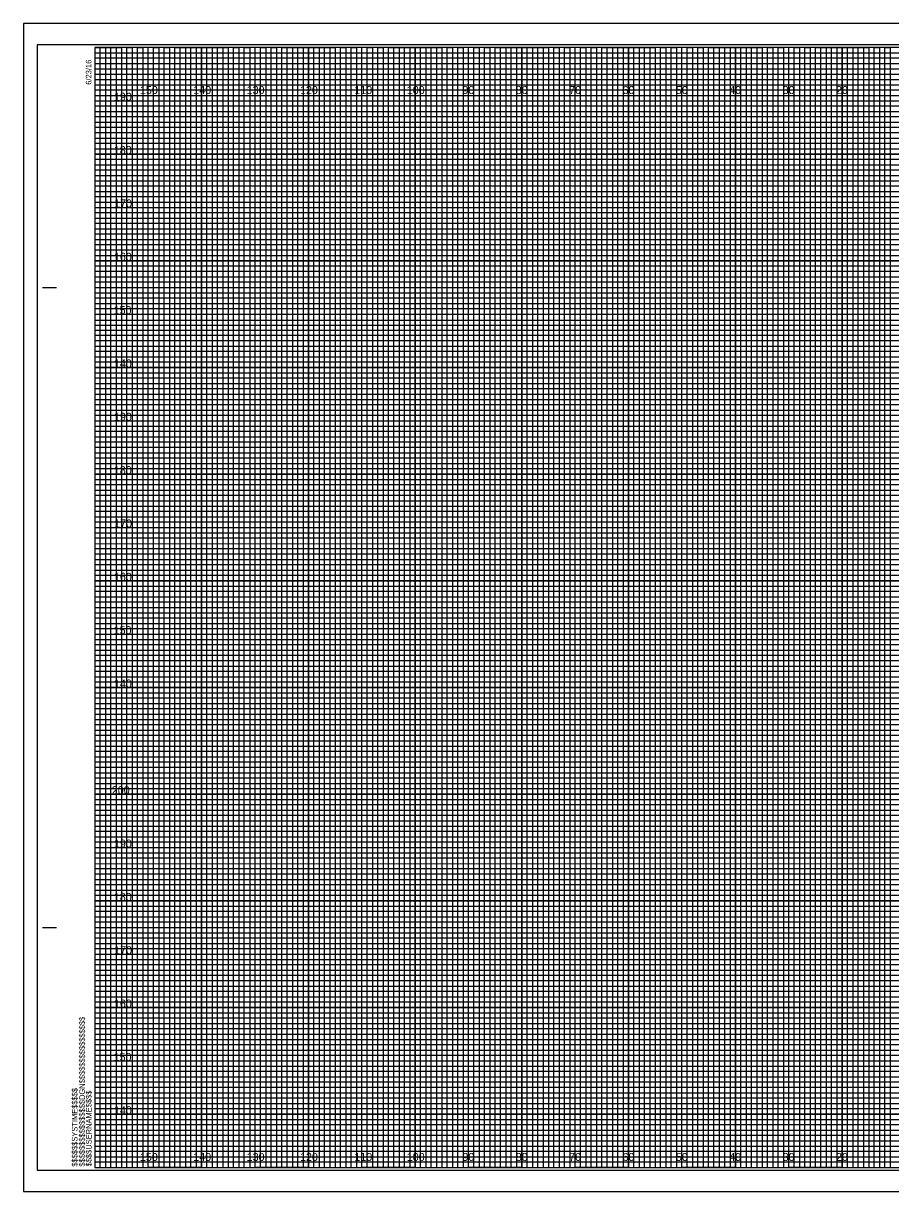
# Model space of a CAD drawing. Extents: x -13 to 323, y -5 to 1754.
# Drawn here: x -13.4 to 149.1, y -4.5 to 214.5 of the extents above; entities that cross this region are included whole.
import ezdxf

# ---------------------------------------------------------------- set-up
doc = ezdxf.new("R2010")
doc.units = 0
for name, color, linetype in [('Exist Cross Section Cell', 7, 'Continuous'), ('Exist XS Center Line Elevation Label', 7, 'Continuous'), ('Exist XS Ground Line', 7, 'Continuous'), ('Prop CMT Pvmt Course 1', 7, 'Continuous'), ('Prop CMT Pvmt Course 2', 7, 'Continuous'), ('Prop CMT Pvmt Course 3', 7, 'Continuous'), ('Prop CMT Shld Paved Course 1', 7, 'Continuous'), ('Prop CMT Shld Paved Course 2', 7, 'Continuous'), ('Prop CMT Subgrade Earthwork', 7, 'Continuous'), ('Prop XS Ditch Standard Text', 7, 'Continuous'), ('Scratch_Level_0', 7, 'Continuous')]:
    doc.layers.add(name, color=color, linetype=linetype)

msp = doc.modelspace()

# ---------------------------------------------------------------- linework, layer by layer
at = {"layer": 'Exist XS Center Line Elevation Label'}
for points in [[(0, 210), (5, 210), (5, 0), (15, 0), (15, 210), (25, 210), (25, 0), (35, 0), (35, 210), (45, 210), (45, 0), (55, 0), (55, 210), (65, 210), (65, 0), (75, 0), (75, 210), (85, 210), (85, 0), (95, 0), (95, 210), (105, 210), (105, 0), (115, 0), (115, 210), (125, 210), (125, 0), (135, 0), (135, 210), (145, 210), (145, 0), (155, 0)], [(0, 205), (275, 205)], [(0, 185), (320, 185), (320, 195), (0, 195)], [(0, 165), (320, 165), (320, 175), (0, 175)], [(0, 145), (320, 145), (320, 155), (0, 155)], [(0, 125), (320, 125), (320, 135), (0, 135)], [(0, 105), (320, 105), (320, 115), (0, 115)], [(0, 85), (320, 85), (320, 95), (0, 95)], [(0, 65), (320, 65), (320, 75), (0, 75)], [(0, 45), (320, 45), (320, 55), (0, 55)], [(0, 25), (320, 25), (320, 35), (0, 35)], [(0, 5), (320, 5), (320, 15), (0, 15)]]:
    msp.add_lwpolyline(points, dxfattribs=at)
at = {"layer": 'Exist XS Ground Line'}
for p, q in [((10, 210), (0, 210)), ((10, 0), (10, 210)), ((30, 210), (20, 210)), ((20, 210), (20, 0)), ((30, 0), (30, 210)), ((50, 210), (40, 210)), ((40, 210), (40, 0)), ((50, 0), (50, 210)), ((70, 210), (60, 210)), ((60, 210), (60, 0)), ((70, 0), (70, 210)), ((90, 210), (80, 210)), ((80, 210), (80, 0)), ((90, 0), (90, 210)), ((110, 210), (100, 210)), ((100, 210), (100, 0)), ((110, 0), (110, 210)), ((130, 210), (120, 210)), ((120, 210), (120, 0)), ((130, 0), (130, 210)), ((150, 210), (140, 210)), ((140, 210), (140, 0)), ((20, 0), (10, 0)), ((40, 0), (30, 0)), ((60, 0), (50, 0)), ((80, 0), (70, 0)), ((100, 0), (90, 0)), ((120, 0), (110, 0)), ((140, 0), (130, 0))]:
    msp.add_line(p, q, dxfattribs=at)
for points in [[(0, 200), (320, 200), (320, 190), (0, 190)], [(0, 180), (320, 180), (320, 170), (0, 170)], [(0, 160), (320, 160), (320, 150), (0, 150)], [(0, 140), (320, 140), (320, 130), (0, 130)], [(0, 120), (320, 120), (320, 110), (0, 110)], [(0, 100), (320, 100), (320, 90), (0, 90)], [(0, 80), (320, 80), (320, 70), (0, 70)], [(0, 60), (320, 60), (320, 50), (0, 50)], [(0, 40), (320, 40), (320, 30), (0, 30)], [(0, 20), (320, 20), (320, 10), (0, 10)]]:
    msp.add_lwpolyline(points, dxfattribs=at)
at = {"layer": 'Prop CMT Pvmt Course 1'}
for p, q in [((323.3, 214.5), (-13.4, 214.5)), ((-13.4, 214.5), (-13.4, -4.5)), ((-13.4, -4.5), (323.3, -4.5))]:
    msp.add_line(p, q, dxfattribs=at)
at = {"layer": 'Prop CMT Pvmt Course 2'}
msp.add_lwpolyline([(-13.4, -4.5), (323.3, -4.5), (323.3, 214.5), (-13.4, 214.5)], close=True, dxfattribs=at)
at = {"layer": 'Prop CMT Pvmt Course 3'}
msp.add_lwpolyline([(-10.8, -0.5), (322.4, -0.5), (322.4, 210.5), (-10.8, 210.5)], close=True, dxfattribs=at)
at = {"layer": 'Prop CMT Shld Paved Course 1'}
for p, q in [((-9.8, 165), (-7.3, 165)), ((-9.7, 165), (-7.2, 165)), ((-9.8, 45), (-7.3, 45)), ((-9.7, 45), (-7.2, 45)), ((0, 0), (0, 0)), ((0, 0), (0, 0)), ((0, 0), (0, 0)), ((0, 0), (0, 0)), ((0, 0), (0, 0)), ((0, 0), (0, 0)), ((0, 0), (0, 0))]:
    msp.add_line(p, q, dxfattribs=at)
msp.add_lwpolyline([(320, 210), (0, 210), (0, 0), (320, 0)], close=True, dxfattribs=at)
at = {"layer": 'Prop CMT Shld Paved Course 2'}
for points in [[(0, 0), (1, 0), (1, 210), (2, 210), (2, 0)], [(2, 0), (3, 0), (3, 210), (4, 210), (4, 0)], [(5, 0), (6, 0), (6, 210), (7, 210), (7, 0)], [(7, 0), (8, 0), (8, 210), (9, 210), (9, 0)], [(10, 0), (11, 0), (11, 210), (12, 210), (12, 0)], [(12, 0), (13, 0), (13, 210), (14, 210), (14, 0)], [(15, 0), (16, 0), (16, 210), (17, 210), (17, 0)], [(17, 0), (18, 0), (18, 210), (19, 210), (19, 0)], [(20, 0), (21, 0), (21, 210), (22, 210), (22, 0)], [(22, 0), (23, 0), (23, 210), (24, 210), (24, 0)], [(25, 0), (26, 0), (26, 210), (27, 210), (27, 0)], [(27, 0), (28, 0), (28, 210), (29, 210), (29, 0)], [(30, 0), (31, 0), (31, 210), (32, 210), (32, 0)], [(32, 0), (33, 0), (33, 210), (34, 210), (34, 0)], [(35, 0), (36, 0), (36, 210), (37, 210), (37, 0)], [(37, 0), (38, 0), (38, 210), (39, 210), (39, 0)], [(40, 0), (41, 0), (41, 210), (42, 210), (42, 0)], [(42, 0), (43, 0), (43, 210), (44, 210), (44, 0)], [(45, 0), (46, 0), (46, 210), (47, 210), (47, 0)], [(47, 0), (48, 0), (48, 210), (49, 210), (49, 0)], [(50, 0), (51, 0), (51, 210), (52, 210), (52, 0)], [(52, 0), (53, 0), (53, 210), (54, 210), (54, 0)], [(55, 0), (56, 0), (56, 210), (57, 210), (57, 0)], [(57, 0), (58, 0), (58, 210), (59, 210), (59, 0)], [(60, 0), (61, 0), (61, 210), (62, 210), (62, 0)], [(62, 0), (63, 0), (63, 210), (64, 210), (64, 0)], [(65, 0), (66, 0), (66, 210), (67, 210), (67, 0)], [(67, 0), (68, 0), (68, 210), (69, 210), (69, 0)], [(70, 0), (71, 0), (71, 210), (72, 210), (72, 0)], [(72, 0), (73, 0), (73, 210), (74, 210), (74, 0)], [(75, 0), (76, 0), (76, 210), (77, 210), (77, 0)], [(77, 0), (78, 0), (78, 210), (79, 210), (79, 0)], [(80, 0), (81, 0), (81, 210), (82, 210), (82, 0)], [(82, 0), (83, 0), (83, 210), (84, 210), (84, 0)], [(85, 0), (86, 0), (86, 210), (87, 210), (87, 0)], [(87, 0), (88, 0), (88, 210), (89, 210), (89, 0)], [(90, 0), (91, 0), (91, 210), (92, 210), (92, 0)], [(92, 0), (93, 0), (93, 210), (94, 210), (94, 0)], [(95, 0), (96, 0), (96, 210), (97, 210), (97, 0)], [(97, 0), (98, 0), (98, 210), (99, 210), (99, 0)], [(100, 0), (101, 0), (101, 210), (102, 210), (102, 0)], [(102, 0), (103, 0), (103, 210), (104, 210), (104, 0)], [(105, 0), (106, 0), (106, 210), (107, 210), (107, 0)], [(107, 0), (108, 0), (108, 210), (109, 210), (109, 0)], [(110, 0), (111, 0), (111, 210), (112, 210), (112, 0)], [(112, 0), (113, 0), (113, 210), (114, 210), (114, 0)], [(115, 0), (116, 0), (116, 210), (117, 210), (117, 0)], [(117, 0), (118, 0), (118, 210), (119, 210), (119, 0)], [(120, 0), (121, 0), (121, 210), (122, 210), (122, 0)], [(122, 0), (123, 0), (123, 210), (124, 210), (124, 0)], [(125, 0), (126, 0), (126, 210), (127, 210), (127, 0)], [(127, 0), (128, 0), (128, 210), (129, 210), (129, 0)], [(130, 0), (131, 0), (131, 210), (132, 210), (132, 0)], [(132, 0), (133, 0), (133, 210), (134, 210), (134, 0)], [(135, 0), (136, 0), (136, 210), (137, 210), (137, 0)], [(137, 0), (138, 0), (138, 210), (139, 210), (139, 0)], [(140, 0), (141, 0), (141, 210), (142, 210), (142, 0)], [(142, 0), (143, 0), (143, 210), (144, 210), (144, 0)], [(145, 0), (146, 0), (146, 210), (147, 210), (147, 0)], [(147, 0), (148, 0), (148, 210), (149, 210), (149, 0)]]:
    msp.add_lwpolyline(points, dxfattribs=at)
at = {"layer": 'Prop CMT Subgrade Earthwork'}
for p, q in [((10, 0), (10, 210)), ((20, 0), (20, 210)), ((30, 0), (30, 210)), ((40, 0), (40, 210)), ((50, 0), (50, 210)), ((60, 0), (60, 210)), ((70, 0), (70, 210)), ((80, 0), (80, 210)), ((90, 0), (90, 210)), ((100, 0), (100, 210)), ((110, 0), (110, 210)), ((120, 0), (120, 210)), ((130, 0), (130, 210)), ((140, 0), (140, 210)), ((0, 200), (320, 200)), ((0, 190), (320, 190)), ((0, 180), (320, 180)), ((0, 170), (320, 170)), ((0, 160), (320, 160)), ((0, 150), (320, 150)), ((0, 140), (320, 140)), ((0, 130), (320, 130)), ((0, 120), (320, 120)), ((0, 110), (320, 110)), ((0, 100), (320, 100)), ((0, 90), (320, 90)), ((0, 80), (320, 80)), ((0, 70), (320, 70)), ((0, 60), (320, 60)), ((0, 50), (320, 50)), ((0, 40), (320, 40)), ((0, 30), (320, 30)), ((0, 20), (320, 20)), ((0, 10), (320, 10))]:
    msp.add_line(p, q, dxfattribs=at)
at = {"layer": 'Scratch_Level_0'}
for p, q in [((0, 209), (260, 209)), ((260, 207.98), (0, 207.98)), ((0, 207.98), (0, 207)), ((0, 207), (260, 207)), ((260, 205.89), (0, 205.89)), ((0, 205.89), (0, 204)), ((0, 204), (320, 204))]:
    msp.add_line(p, q, dxfattribs=at)
for points in [[(0, 203), (270, 203), (320, 203), (320, 202), (0, 202)], [(0, 201), (320, 201), (320, 199), (0, 199)], [(0, 198), (320, 198), (320, 197), (0, 196.98)], [(0, 196), (320, 196), (320, 194), (0, 194)], [(0, 193), (320, 193), (320, 192), (0, 192)], [(0, 191), (320, 191), (320, 189), (0, 189)], [(0, 188), (320, 188), (320, 187), (0, 187)], [(0, 186), (320, 186), (320, 184), (0, 184)], [(0, 183), (320, 183), (320, 182), (0, 182)], [(0, 181), (320, 181), (320, 179), (0, 179)], [(0, 178), (320, 178), (320, 177), (0, 177)], [(0, 176), (320, 176), (320, 173.95), (320, 173), (320, 172), (0, 172)], [(0, 174), (320, 174), (320, 173), (0, 173)], [(0, 171), (320, 171), (320, 169), (0, 169.03)], [(0, 169.03), (320, 169), (320, 168), (0, 168)], [(0, 167), (320, 167), (320, 166), (0, 166)], [(0, 164), (320, 164), (320, 163), (0, 163)], [(0, 162), (320, 162), (320, 161), (0, 161)], [(-0.07, 158.89), (320, 158.89), (320, 157.88), (-0.07, 157.88)], [(0, 157), (320, 157), (320, 156), (0, 156)], [(0, 154), (320, 154), (320, 153), (0, 153)], [(0, 152), (320, 152), (320, 151), (0, 151)], [(0, 149), (320, 149), (320, 148), (0, 148)], [(0, 147), (320, 147), (320, 146), (0, 146)], [(0, 144), (320, 144), (320, 143), (0, 143)], [(0, 142), (320, 142), (320, 141), (0, 141)], [(0, 139), (320, 139), (319.99, 137.98), (0, 138)], [(0, 137), (320, 137), (320, 136), (0, 136)], [(0, 134), (320, 134), (320, 133), (0, 133)], [(0, 132), (320, 132), (320, 131), (0, 131)], [(0, 129), (320, 129), (320, 128), (0, 128)], [(0, 127), (320, 127), (320, 126), (0, 126)], [(0, 124), (320, 124), (320, 123), (0, 123)], [(0, 122), (320, 122), (320, 121), (0, 121)], [(0, 119), (320, 119), (320, 118), (0, 118)], [(0, 116.99), (320.07, 116.91), (320, 116), (0, 116)], [(0, 114), (320, 114), (320, 113), (0, 113)], [(0, 112), (320, 112), (320, 111), (0, 111)], [(0, 109), (320, 109), (320, 108), (0, 108)], [(0, 107), (320, 107), (320, 106), (0, 106)], [(0, 104), (320, 104), (320, 103), (0, 103)], [(0, 102), (320, 102), (320, 101), (0, 101)], [(0, 99), (320, 99), (320, 98), (0, 98)], [(0, 97), (320, 97), (320, 96), (0, 96)], [(0, 94), (320, 94), (320, 93), (0, 93)], [(0, 92), (320, 92), (320, 91), (0, 91)], [(0, 89), (320, 89), (320, 88), (0, 88)], [(0, 87), (320, 87), (320, 86), (0, 86)], [(0, 84), (320, 84), (320, 83), (0, 83)], [(0, 82), (320, 82), (320, 81), (0, 81)], [(0, 79), (320, 79), (319.99, 77.98), (0, 78)], [(0, 77), (320, 77), (320, 76), (0, 76)], [(0, 74), (320, 74), (320, 73), (0, 73)], [(0, 72), (320, 72), (320, 71), (0, 71)], [(0, 69), (320, 69), (320, 68), (0, 68)], [(0, 67), (320, 67), (320, 66), (0, 66)], [(0, 64), (320, 64), (320, 63), (0, 63)], [(0, 62), (320, 62), (320, 61), (0, 61)], [(0, 59), (320, 59), (320, 58), (0, 58)], [(0, 56.99), (320.07, 56.91), (320, 56), (0, 56)], [(0, 54), (320, 54), (320, 53), (0, 53)], [(0, 52), (320, 52), (320, 51), (0, 51)], [(0, 49), (320, 49), (320, 48), (0, 48)], [(0, 47), (320, 47), (320, 46), (0, 46)], [(0, 44), (320, 44), (320, 43), (0, 43)], [(0, 42), (320, 42), (320, 41), (0, 41)], [(0, 39), (320, 39), (320, 38), (0, 38)], [(0, 37), (320, 37), (320, 36), (0, 36)], [(0, 34), (320, 34), (320, 33), (0, 33)], [(0, 32), (320, 32), (320, 31), (0, 31)], [(0, 29), (320, 29), (320, 28), (0, 28)], [(0, 27), (320, 27), (320, 26), (0, 26)], [(0, 24), (320, 24), (320, 23), (0, 23)], [(0, 22), (320, 22), (320, 21), (0, 21)], [(0, 19), (320, 19), (320, 18), (0, 18)], [(0, 17), (320, 17), (320, 16), (0, 16)], [(0, 14), (320, 14), (320, 13), (0, 13)], [(0, 12), (320, 12), (320, 11), (0, 11)], [(0, 9), (320, 9), (320, 8), (0, 8)], [(0, 7), (320, 7), (320, 6), (0, 6)], [(0, 4), (320, 4), (320, 3), (0, 3)], [(0, 2), (320, 2), (320, 1), (0, 1)]]:
    msp.add_lwpolyline(points, dxfattribs=at)

# ---------------------------------------------------------------- texts
at = {"layer": 'Exist Cross Section Cell'}
for s, p in [('190', (3.57, 200)), ('180', (3.55, 190)), ('170', (3.61, 180)), ('160', (3.57, 170)), ('150', (3.52, 160)), ('140', (3.57, 150)), ('190', (3.57, 140)), ('180', (3.55, 130)), ('170', (3.61, 120)), ('160', (3.57, 110)), ('150', (3.52, 100)), ('140', (3.57, 90)), ('200', (3.17, 70)), ('190', (3.57, 60)), ('180', (3.55, 50)), ('170', (3.61, 40)), ('160', (3.57, 30)), ('150', (3.52, 20)), ('140', (3.57, 10))]:
    msp.add_text(s, height=1.5, dxfattribs=at).set_placement(p)
at = {"layer": 'Prop CMT Shld Paved Course 1'}
for s, p in [('6/23/16', (-0.65, 203)), ('$$$$$$$$$$$$$$$$DGN$$$$$$$$$$$$$$$$', (-1.88, 0.18)), ('$$$$$$SYSTIME$$$$$', (-3.26, 0.18)), ('$$$$USERNAME$$$$', (-0.62, 0.23))]:
    msp.add_text(s, height=1.05, rotation=90, dxfattribs=at).set_placement(p)
at = {"layer": 'Prop XS Ditch Standard Text'}
for s, p in [('150', (8.44, 201.25)), ('140', (18.44, 201.25)), ('130', (28.44, 201.25)), ('120', (38.44, 201.25)), ('110', (48.62, 201.25)), ('100', (58.44, 201.25)), ('90', (68.86, 201.25)), ('80', (78.86, 201.25)), ('70', (88.86, 201.25)), ('60', (98.86, 201.25)), ('50', (108.86, 201.25)), ('40', (118.86, 201.25)), ('30', (128.86, 201.25)), ('20', (138.86, 201.25)), ('150', (8.44, 1.25)), ('140', (18.44, 1.25)), ('130', (28.44, 1.25)), ('120', (38.44, 1.25)), ('110', (48.62, 1.25)), ('100', (58.44, 1.25)), ('90', (68.86, 1.25)), ('80', (78.86, 1.25)), ('70', (88.86, 1.25)), ('60', (98.86, 1.25)), ('50', (108.86, 1.25)), ('40', (118.86, 1.25)), ('30', (128.86, 1.25)), ('20', (138.86, 1.25))]:
    msp.add_text(s, height=1.5, dxfattribs=at).set_placement(p)

doc.saveas('drawing.dxf')
